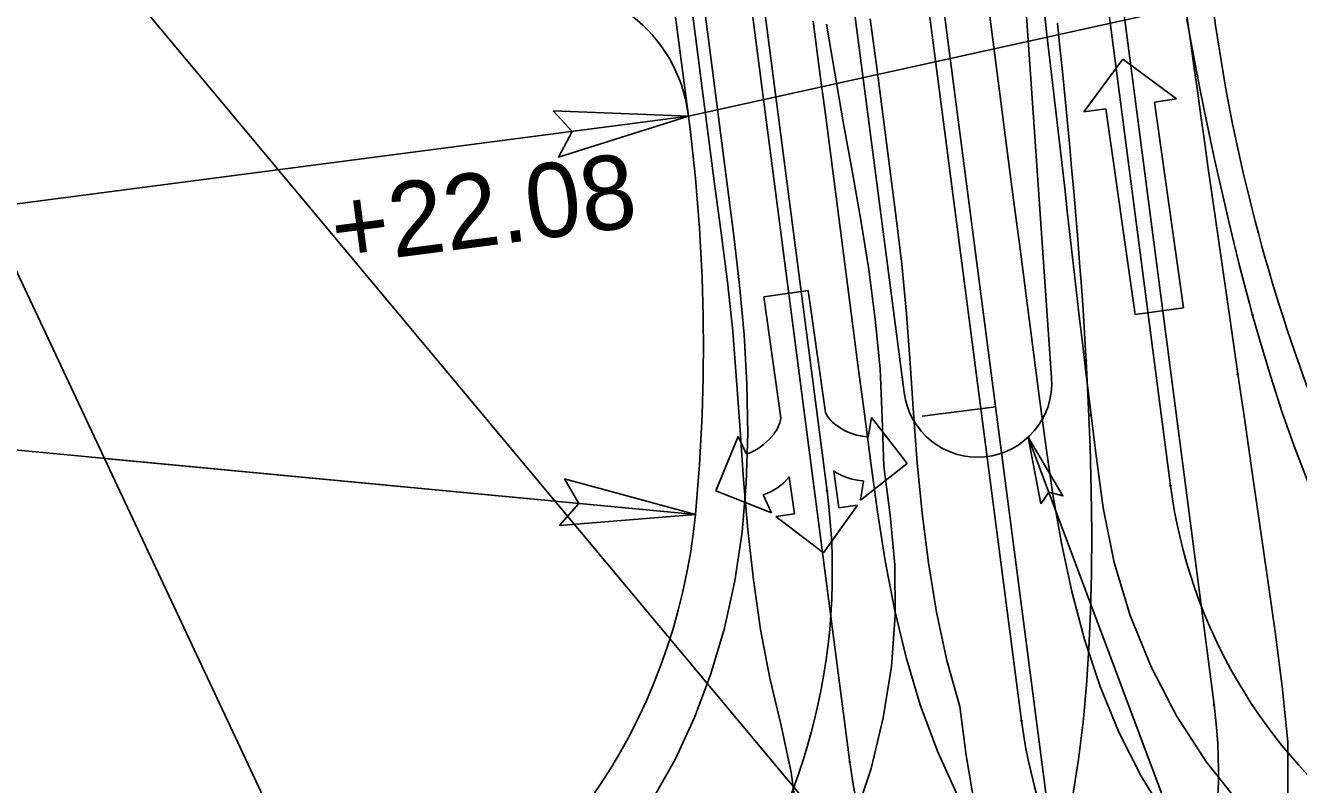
# Model space of a CAD drawing. Extents: x 2367848 to 2369479, y 800728 to 808616.
# Drawn here: x 2368309.8 to 2368395.5, y 807974.9 to 808026 of the extents above; entities that cross this region are included whole.
import ezdxf

# ---------------------------------------------------------------- set-up
doc = ezdxf.new("R2010")
doc.units = 0
for name, color, linetype in [('Prop AutoTurn Projected Path', 7, 'Continuous'), ('Prop AutoTurn Simulation', 7, 'Continuous'), ('Prop Conc 5in Monolithic Surface Mount Island', 7, 'Continuous'), ('Prop Dimension', 7, 'Continuous'), ('Prop Dimension Text', 7, 'Continuous'), ('Prop EOT', 7, 'Continuous'), ('Prop Horizontal Alignment', 7, 'Continuous'), ('Prop Horizontal Alignment Station Label', 7, 'Continuous'), ('Prop Horizontal Alignment Tick Small', 7, 'Continuous'), ('Prop Lane Arrow CELL', 7, 'Continuous'), ('Prop Terminator CELL', 7, 'Continuous'), ('Scratch_Level_1', 7, 'Continuous'), ('Scratch_Level_3', 7, 'Continuous')]:
    doc.layers.add(name, color=color, linetype=linetype)

msp = doc.modelspace()

# ---------------------------------------------------------------- linework, layer by layer
at = {"layer": 'Prop AutoTurn Projected Path'}
for p, q in [((2368386.918, 807995.035), (2368377.058, 808070.767)), ((2368376.879, 807979.194), (2368365.158, 808069.218)), ((2368363.77, 807994.679), (2368354.25, 808067.798))]:
    msp.add_line(p, q, dxfattribs=at)
for centre, radius, start, end in [((2368322.121, 807989.257), 42, 279.34665, 7.41804), ((2368421.625, 807999.554), 35, 187.41804, 279.34665), ((2368421.625, 807999.554), 35, 187.41804, 279.34665), ((2368411.586, 807983.713), 35, 187.41804, 279.34665)]:
    msp.add_arc(centre, radius, start, end, dxfattribs=at)
at = {"layer": 'Prop AutoTurn Simulation'}
for points in [[(2368355.345, 808028.408), (2368355.776, 808025.1), (2368356.206, 808021.791), (2368356.637, 808018.483), (2368357.068, 808015.174), (2368357.49, 808011.865), (2368357.871, 808008.55), (2368358.176, 808005.228), (2368358.372, 808001.898), (2368358.432, 807998.563), (2368358.329, 807995.229), (2368358.04, 807991.907), (2368357.548, 807988.623), (2368356.851, 807985.436), (2368355.95, 807982.365), (2368354.85, 807979.426), (2368353.558, 807976.632), (2368352.084, 807973.994)], [(2368374.618, 808027.539), (2368375.049, 808024.229), (2368375.48, 808020.919), (2368375.911, 808017.61), (2368376.342, 808014.3), (2368376.773, 808010.99), (2368377.204, 808007.681), (2368377.635, 808004.371), (2368378.066, 808001.061), (2368378.504, 807997.753), (2368378.988, 807994.45), (2368379.56, 807991.162), (2368380.259, 807987.899), (2368381.118, 807984.676), (2368382.169, 807981.51), (2368383.436, 807978.425), (2368384.931, 807975.463), (2368386.633, 807972.698)], [(2368381.559, 807999.794), (2368381.427, 808000.884), (2368381.211, 808002.692), (2368380.999, 808004.49), (2368380.791, 808006.277), (2368380.586, 808008.054), (2368380.384, 808009.822), (2368380.182, 808011.582), (2368379.982, 808013.334), (2368379.783, 808015.079), (2368379.584, 808016.816), (2368379.386, 808018.548), (2368379.187, 808020.273), (2368378.988, 808021.993), (2368378.789, 808023.707), (2368378.589, 808025.417), (2368378.389, 808027.123)], [(2368363.732, 808026.136), (2368364.284, 808022.842), (2368364.862, 808019.548), (2368365.472, 808016.249), (2368366.057, 808012.937), (2368366.583, 808009.606), (2368367.02, 808006.262), (2368367.345, 808002.919), (2368367.478, 807999.615), (2368367.585, 807996.356), (2368368.016, 807993.048), (2368368.331, 807989.7), (2368368.36, 807986.29), (2368368.102, 807982.848), (2368367.559, 807979.402), (2368366.733, 807975.979), (2368365.629, 807972.607)], [(2368366.685, 808026.506), (2368367.116, 808023.196), (2368367.547, 808019.887), (2368367.978, 808016.577), (2368368.409, 808013.267), (2368368.82, 808009.955), (2368369.116, 808006.626), (2368369.376, 808003.288), (2368369.595, 807999.934), (2368369.845, 807996.568), (2368370.168, 807993.196), (2368370.598, 807989.835), (2368371.155, 807986.51), (2368371.846, 807983.262), (2368372.718, 807980.17), (2368373.149, 807976.861), (2368373.695, 807973.546)], [(2368392.444, 808006.53), (2368392.229, 808007.315), (2368391.874, 808008.652), (2368391.522, 808010.021), (2368391.175, 808011.419), (2368390.832, 808012.842), (2368390.496, 808014.289), (2368390.165, 808015.756), (2368389.839, 808017.242), (2368389.52, 808018.744), (2368389.207, 808020.261), (2368388.899, 808021.792), (2368388.596, 808023.334), (2368388.299, 808024.886), (2368388.007, 808026.448)], [(2368413.052, 807974.6), (2368410.426, 807976.092), (2368408.019, 807977.786), (2368405.843, 807979.661), (2368403.908, 807981.693), (2368402.209, 807983.852), (2368400.711, 807986.09), (2368399.38, 807988.377), (2368398.187, 807990.691), (2368397.111, 807993.02), (2368396.135, 807995.356), (2368395.244, 807997.694), (2368394.424, 808000.031), (2368393.668, 808002.364), (2368392.948, 808004.753), (2368392.444, 808006.53)], [(2368391.644, 807973.514), (2368389.346, 807976.417), (2368387.324, 807979.532), (2368385.599, 807982.832), (2368384.189, 807986.288), (2368383.108, 807989.868), (2368382.368, 807993.54), (2368381.877, 807997.235), (2368381.559, 807999.794)]]:
    msp.add_lwpolyline(points, dxfattribs=at)
for centre in [(2368392.444, 808006.53), (2368392.444, 808006.53), (2368381.559, 807999.794), (2368381.559, 807999.794), (2368363.77, 807994.679), (2368363.77, 807994.679), (2368386.918, 807995.035), (2368386.918, 807995.035), (2368376.879, 807979.194), (2368376.879, 807979.194)]:
    msp.add_circle(centre, 0.0417, dxfattribs=at)
at = {"layer": 'Prop Conc 5in Monolithic Surface Mount Island'}
for p, q in [((2368376.763, 808033.309), (2368378.903, 808002.305)), ((2368378.903, 808002.305), (2368376.763, 808033.309)), ((2368368.957, 808001.315), (2368364.975, 808031.896)), ((2368364.975, 808031.896), (2368368.957, 808001.315))]:
    msp.add_line(p, q, dxfattribs=at)
msp.add_arc((2368373.915, 808001.96), 5, 187.41804, 3.94885, dxfattribs=at)
msp.add_arc((2368373.915, 808001.96), 5, 187.41804, 3.94885, dxfattribs=at)
at = {"layer": 'Prop Dimension'}
for p, q in [((2368281.057, 808069.281), (2368332.09, 807960.673)), ((2368235.437, 808004.433), (2368354.9, 807993.097)), ((2368393.103, 807956.171), (2368377.329, 807998.308)), ((2368315.079, 807996.876), (2368354.9, 807993.097)), ((2368315.079, 807996.876), (2368332.09, 807960.673))]:
    msp.add_line(p, q, dxfattribs=at)
at = {"layer": 'Prop Dimension Text'}
msp.add_line((2368235.437, 808004.433), (2368354.432, 808019.926), dxfattribs=at)
at = {"layer": 'Prop EOT'}
msp.add_line((2368354.432, 808019.926), (2368348.245, 808067.447), dxfattribs=at)
for centre, radius, start, end in [((2368344.496, 808018.792), 10, 7.41804, 96.82936), ((2368508.719, 808043.195), 120, 187.41804, 200.2566), ((2368235.437, 808004.433), 120, 354.57947, 7.41804), ((2368315.079, 807996.876), 40, 295.16773, 354.57947)]:
    msp.add_arc(centre, radius, start, end, dxfattribs=at)
at = {"layer": 'Prop Horizontal Alignment'}
msp.add_line((2368427.272, 807599.886), (2368315.244, 808460.338), dxfattribs=at)
at = {"layer": 'Prop Horizontal Alignment Station Label'}
msp.add_line((2368381.597, 807950.7), (2368243.014, 808116.668), dxfattribs=at)
at = {"layer": 'Prop Horizontal Alignment Tick Small'}
msp.add_line((2368375.132, 808000.357), (2368370.174, 807999.712), dxfattribs=at)
at = {"layer": 'Prop Lane Arrow CELL'}
for p, q in [((2368381.078, 808020.22), (2368383.708, 808023.772)), ((2368383.708, 808023.772), (2368387.317, 808021.1)), ((2368387.317, 808021.1), (2368385.831, 808020.89)), ((2368382.564, 808020.429), (2368381.078, 808020.22)), ((2368384.52, 808006.567), (2368382.564, 808020.429)), ((2368385.831, 808020.89), (2368387.788, 808007.028)), ((2368359.503, 808007.758), (2368362.495, 808008.182)), ((2368362.495, 808008.182), (2368363.657, 807999.976)), ((2368360.657, 807999.601), (2368359.503, 808007.758)), ((2368387.788, 808007.028), (2368384.52, 808006.567)), ((2368366.55, 807998.318), (2368366.759, 807999.627)), ((2368366.759, 807999.627), (2368369.168, 807996.522)), ((2368356.28, 807994.698), (2368357.781, 807998.357)), ((2368357.781, 807998.357), (2368358.345, 807997.156)), ((2368364.217, 807996.018), (2368364.566, 807993.556)), ((2368369.168, 807996.522), (2368366.021, 807994.058)), ((2368361.573, 807993.133), (2368361.218, 807995.643)), ((2368366.021, 807994.058), (2368366.229, 807995.367)), ((2368360.036, 807993.211), (2368356.28, 807994.698)), ((2368359.472, 807994.411), (2368360.036, 807993.211)), ((2368365.821, 807993.734), (2368363.521, 807990.504)), ((2368364.566, 807993.556), (2368365.821, 807993.734)), ((2368360.318, 807992.955), (2368361.573, 807993.133)), ((2368363.521, 807990.504), (2368360.318, 807992.955))]:
    msp.add_line(p, q, dxfattribs=at)
for centre, radius, start, end in [((2368358.403, 807999.934), 2.275, 317.1291, 351.89512), ((2368365.703, 808000.967), 2.275, 205.98486, 238.98281), ((2368366.794, 808002.31), 3.996, 235.49272, 266.70539), ((2368356.982, 808000.921), 3.996, 289.68904, 320.61918), ((2368366.433, 807999.354), 3.996, 236.29918, 267.07565), ((2368358.15, 807998.182), 3.996, 289.31985, 320.20954)]:
    msp.add_arc(centre, radius, start, end, dxfattribs=at)
at = {"layer": 'Prop Terminator CELL'}
for points in [[(2368345.307, 808020.3), (2368354.432, 808019.926), (2368345.665, 808017.17), (2368346.599, 808018.905)], [(2368378.181, 807993.821), (2368377.329, 807998.308), (2368379.665, 807994.35), (2368378.714, 807994.608)], [(2368346.087, 807995.491), (2368354.9, 807993.097), (2368345.739, 807992.359), (2368347.035, 807993.844)]]:
    msp.add_lwpolyline(points, close=True, dxfattribs=at)
at = {"layer": 'Scratch_Level_1'}
for p, q in [((2368389.849, 807980.271), (2368377.994, 808071.32)), ((2368353.386, 808067.958), (2368365.308, 807976.394))]:
    msp.add_line(p, q, dxfattribs=at)
for points in [[(2368354.477, 808028.601), (2368354.907, 808025.296), (2368355.338, 808021.99), (2368355.768, 808018.685), (2368356.198, 808015.379), (2368356.629, 808012.073), (2368357.059, 808008.768), (2368357.416, 808005.452), (2368357.669, 808002.12), (2368357.92, 807998.781), (2368358.149, 807995.424), (2368358.432, 807992.059), (2368358.805, 807988.694), (2368359.297, 807985.352), (2368359.921, 807982.064), (2368360.674, 807978.875), (2368361.363, 807975.712), (2368361.81, 807972.404)], [(2368362.84, 808026.329), (2368363.271, 808023.023), (2368363.701, 808019.717), (2368364.131, 808016.412), (2368364.562, 808013.106), (2368364.992, 808009.801), (2368365.423, 808006.495), (2368365.853, 808003.189), (2368366.283, 807999.884), (2368366.715, 807996.578), (2368367.17, 807993.276), (2368367.693, 807989.984), (2368368.323, 807986.711), (2368369.098, 807983.47), (2368370.049, 807980.277), (2368371.204, 807977.152), (2368372.585, 807974.122)], [(2368381.23, 808003.456), (2368381.212, 808003.767), (2368381.118, 808005.326), (2368381.016, 808006.896), (2368380.905, 808008.474), (2368380.788, 808010.061), (2368380.663, 808011.654), (2368380.532, 808013.254), (2368380.395, 808014.859), (2368380.252, 808016.469), (2368380.104, 808018.084), (2368379.951, 808019.702), (2368379.793, 808021.324), (2368379.631, 808022.949), (2368379.465, 808024.577), (2368379.296, 808026.208)], [(2368391.452, 808002.548), (2368391.402, 808002.894), (2368391.15, 808004.621), (2368390.9, 808006.342), (2368390.652, 808008.057), (2368390.405, 808009.768), (2368390.16, 808011.474), (2368389.916, 808013.176), (2368389.675, 808014.875), (2368389.434, 808016.57), (2368389.195, 808018.261), (2368388.958, 808019.95), (2368388.722, 808021.636), (2368388.487, 808023.32), (2368388.254, 808025.002), (2368388.022, 808026.681)], [(2368380.304, 807974.032), (2368380.707, 807976.578), (2368381.017, 807979.101), (2368381.249, 807981.603), (2368381.415, 807984.082), (2368381.524, 807986.543), (2368381.587, 807989.121), (2368381.603, 807991.854), (2368381.572, 807994.709), (2368381.494, 807997.659), (2368381.373, 808000.684), (2368381.23, 808003.456)], [(2368394.822, 807974.044), (2368394.806, 807977.782), (2368394.444, 807981.507), (2368393.954, 807985.182), (2368393.448, 807988.805), (2368392.935, 807992.383), (2368392.421, 807995.92), (2368391.909, 807999.422), (2368391.452, 808002.548)]]:
    msp.add_lwpolyline(points, dxfattribs=at)
for centre in [(2368381.23, 808003.456), (2368381.23, 808003.456), (2368391.452, 808002.548), (2368391.452, 808002.548), (2368389.849, 807980.271), (2368389.849, 807980.271), (2368365.308, 807976.394), (2368365.308, 807976.394)]:
    msp.add_circle(centre, 0.0417, dxfattribs=at)
for centre, start, end in [((2368355.141, 807975.752), 279.30395, 7.41804), ((2368400.015, 807980.912), 187.41804, 279.30395)]:
    msp.add_arc(centre, 35, start, end, dxfattribs=at)
at = {"layer": 'Scratch_Level_3'}
msp.add_line((2368354.432, 808019.926), (2368389.724, 808027.702), dxfattribs=at)

# ---------------------------------------------------------------- texts
at = {"layer": 'Prop Dimension Text'}
msp.add_text('+22.08', height=5, rotation=7.41804, dxfattribs=at).set_placement((2368330.681, 808009.872))

doc.saveas('drawing.dxf')
